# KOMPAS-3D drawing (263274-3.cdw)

Referenced files in I:\контрольыне\КУРСАЧ\: Муфта.cdw
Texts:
  Муфта
  Loner-XP
  WolfishLair
  Текст на чертеже
  Размерные надписи
  Шероховатость
  Линия-выноска #1
  Линия-выноска #2
  Линия-выноска #3
  Отклонения формы и база
  Заголовок таблицы
  Ячейка таблицы
  Стрелка вида
  Обозначение изменения
  Фигурная скобка
  Номер узла
  Марка координационной оси
  VRCB
  Выносная надпись
  Обозначение узла
  Марка/позиционное обозначение с линией-выноской
  Марка/позиционное обозначение на линии
  Марка/позиционное обозначение без линии-выноски
  Лит-Масса-Масштаб
  Материал-Предприятие
  Title Specification
  Body Specification ( left align )
  Body Specificaton ( centered )
  Техническая характеристика
  Вращающий момент на Быстроходном валу, Н м   35,64
  Допускаемое радиальное смещение валов, мм   0.3
  Допускаемое осевое смещение валов, мм   1
  Допускаемое угловое смещение валов, 1 30
  Symbol
  ВНУ им. Даля
  гр. МЗ - 06в
  Месечко А.В
  Овчаренко В.В.
Dimensions and other numbers on the sheet: 701.48.00.005 ВО; 7; 121; 5; 58; 140; 67; 18; 38; 105; 4; 1:1; 1; 701.48.00.005 ВО-; 0; 2; 3; 6; 8; 9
